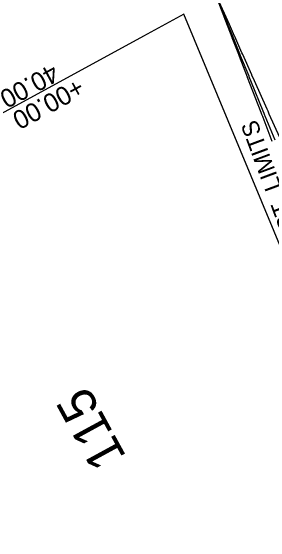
# Model space of a CAD drawing. Extents: x 1627557 to 1636561, y 783843 to 794002.
# Drawn here: x 1627795.3 to 1627879.8, y 785040.7 to 785213.4 of the extents above; entities that cross this region are included whole.
import ezdxf

# ---------------------------------------------------------------- set-up
doc = ezdxf.new("R2010")
doc.units = 0
for name, color, linetype in [('R_Clearzone', 7, 'Continuous'), ('R_Ditch', 7, 'Continuous'), ('R_Horz Alg Annot', 7, 'Continuous'), ('R_Proposed Const Limits', 7, 'Continuous'), ('R_Proposed Const Limits Annot', 7, 'Continuous'), ('R_ROW', 7, 'Continuous'), ('R_ROW Annot', 7, 'Continuous'), ('Transition Dimensions', 7, 'Continuous')]:
    doc.layers.add(name, color=color, linetype=linetype)

msp = doc.modelspace()

# ---------------------------------------------------------------- linework, layer by layer
at = {"layer": 'R_Clearzone'}
msp.add_lwpolyline([(1627882.5, 785172.3), (1627879.12, 785179.91), (1627879, 785180.18), (1627878.72, 785180.81), (1627878.43, 785181.47), (1627874.36, 785190.64), (1627873.53, 785192.49), (1627873.46, 785192.65), (1627870.56, 785199.2), (1627870.29, 785199.8), (1627867.95, 785205.07), (1627867.92, 785205.13), (1627866.22, 785208.97), (1627862.39, 785217.59)], dxfattribs=at)
at = {"layer": 'R_Ditch'}
msp.add_lwpolyline([(1627881, 785171.48), (1627877.85, 785179.22), (1627877.74, 785179.48), (1627877.47, 785180.13), (1627877.2, 785180.8), (1627873.41, 785190.12), (1627872.64, 785192), (1627872.57, 785192.17), (1627869.86, 785198.82), (1627869.61, 785199.44), (1627867.43, 785204.79), (1627867.41, 785204.85), (1627865.81, 785208.76), (1627862.25, 785217.51)], dxfattribs=at)
at = {"layer": 'R_Proposed Const Limits'}
msp.add_lwpolyline([(1627880.12, 785171), (1627877.1, 785178.81), (1627877, 785179.08), (1627876.75, 785179.73), (1627876.49, 785180.41), (1627872.86, 785189.82), (1627872.13, 785191.72), (1627872.06, 785191.89), (1627869.48, 785198.61), (1627869.24, 785199.23), (1627867.16, 785204.64), (1627867.14, 785204.7), (1627865.62, 785208.65), (1627862.22, 785217.5)], dxfattribs=at)
at = {"layer": 'R_ROW'}
msp.add_line((1627959.18, 784952.13), (1627851.48, 785212.33), dxfattribs=at)
at = {"layer": 'R_ROW Annot'}
msp.add_lwpolyline([(1627851.48, 785212.33), (1627790.77, 785179.23)], dxfattribs=at)
at = {"layer": 'Transition Dimensions'}
msp.add_line((1627838.34, 785205.17), (1627704.34, 785132.1), dxfattribs=at)

# ---------------------------------------------------------------- texts
at = {"layer": 'R_Horz Alg Annot'}
msp.add_text('115', height=12, rotation=118.601, dxfattribs=at).set_placement((1627832.96, 785068.73))
at = {"layer": 'R_Proposed Const Limits Annot'}
msp.add_text('CONST. LIMITS', height=5.5, rotation=110.4259, dxfattribs=at).set_placement((1627893.65, 785128.21))
at = {"layer": 'R_ROW Annot'}
for s, p in [('40.00', (1627808.85, 785196.4)), ('+00.00', (1627817.07, 785191.77))]:
    msp.add_text(s, height=6, rotation=208.601, dxfattribs=at).set_placement(p)

doc.saveas('drawing.dxf')
